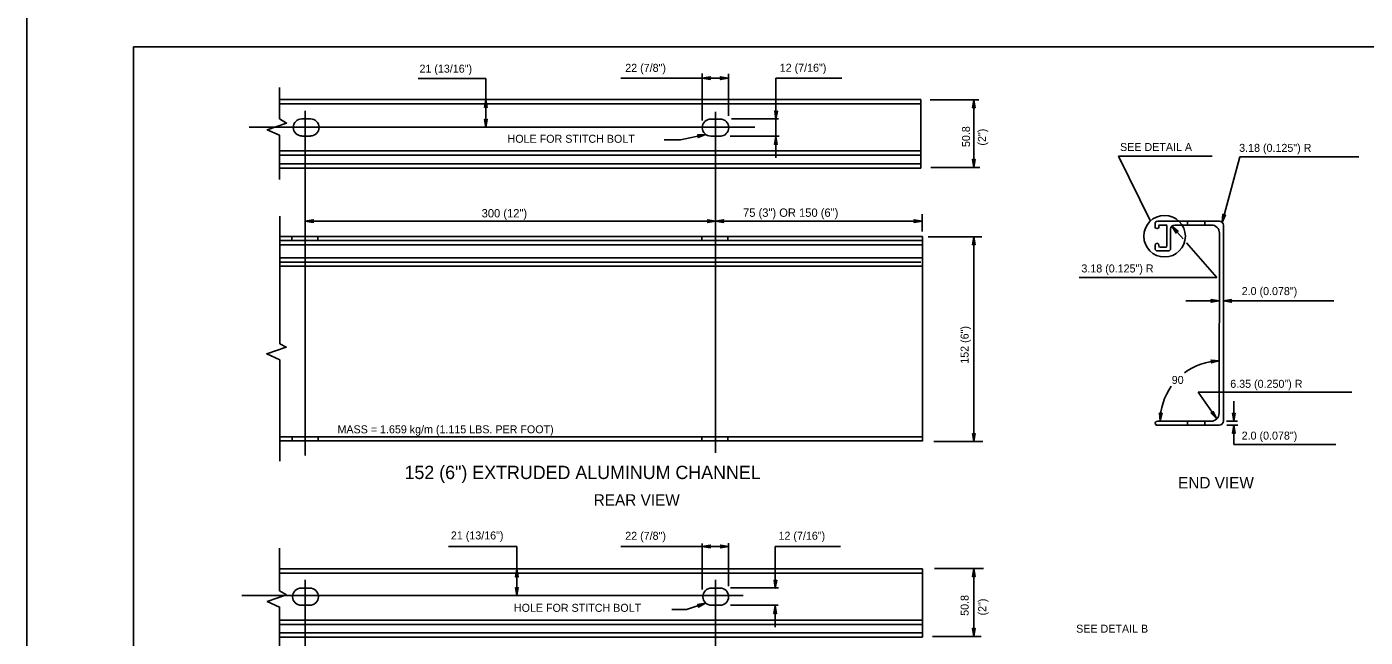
# Model space of a CAD drawing. Extents: x 647822 to 648727, y 298458 to 299646.
# Drawn here: x 647822 to 648324, y 298815 to 299044 of the extents above; entities that cross this region are included whole.
import ezdxf

# ---------------------------------------------------------------- set-up
doc = ezdxf.new("R2010")
doc.units = 0
for name, color, linetype in [('1', 7, 'Continuous'), ('2', 7, 'Continuous'), ('3', 7, 'Continuous'), ('XCS-GRID-MIN', 7, 'Continuous')]:
    doc.layers.add(name, color=color, linetype=linetype)

# ---------------------------------------------------------------- blocks, each defined once
blk = doc.blocks.new('RARROW')
at = {"layer": '3'}
blk.add_lwpolyline([(-2.2695, 0.285), (-2.184875, 0.12075), (0, 0), (-2.2695, 0.285), (-2.38575, 0.384625), (0, 0), (-2.183125, -0.108), (-2.262875, -0.2705), (0, 0), (-2.38575, -0.379125), (-2.262875, -0.2705)], dxfattribs=at)

msp = doc.modelspace()

# ---------------------------------------------------------------- linework, layer by layer
at = {"layer": '1'}
for q in [(648648.31, 299036.63), (647862.31, 298472.63)]:
    msp.add_line((647862.31, 299036.63), q, dxfattribs=at)
at = {"layer": '2'}
for p, q in [((648075.56, 299008.97), (648075.56, 299026.6)), ((648085.44, 299010.72), (648085.44, 299026.48)), ((647917.06, 299021.35), (647917.06, 299009.6)), ((647994.44, 299024.72), (647969.05, 299024.72)), ((647994.44, 299016.47), (647994.44, 299024.72)), ((648075.44, 299024.85), (648045.05, 299024.85)), ((648075.69, 299024.85), (648066.06, 299024.85)), ((648085.31, 299024.85), (648075.56, 299024.85)), ((648085.44, 299024.85), (648085.06, 299024.85)), ((648085.44, 299024.85), (648085.31, 299024.85)), ((648103.19, 299009.47), (648103.19, 299024.85)), ((648127.83, 299024.85), (648103.19, 299024.85)), ((648157.44, 299016.85), (647917.06, 299016.85)), ((648157.44, 299015.22), (647917.06, 299015.22)), ((647994.44, 299006.35), (647994.44, 299016.85)), ((647994.44, 299015.22), (647994.44, 299016.6)), ((648157.44, 299016.85), (648157.44, 298991.1)), ((648179.19, 299016.72), (648160.94, 299016.72)), ((648177.31, 298991.35), (648177.31, 299016.72)), ((647926.69, 298883.22), (647926.69, 299012.6)), ((648080.56, 299012.22), (648080.56, 298884.22)), ((647905.69, 299006.47), (648095.31, 299006.47)), ((647922.19, 299006.35), (647922.19, 299006.35)), ((647922.19, 299006.35), (647922.19, 299006.35)), ((647928.69, 299009.6), (647925.44, 299009.6)), ((647928.69, 299009.6), (647925.44, 299009.6)), ((647927.06, 299006.35), (647927.06, 299006.35)), ((647927.06, 299006.35), (647927.06, 299006.35)), ((647931.94, 299006.35), (647931.94, 299006.35)), ((647931.94, 299006.35), (647931.94, 299006.35)), ((648075.81, 299006.35), (648075.81, 299006.35)), ((648075.81, 299006.35), (648075.81, 299006.35)), ((648076.19, 299006.35), (648076.19, 299006.35)), ((648076.19, 299006.35), (648076.19, 299006.35)), ((648082.31, 299009.47), (648078.69, 299009.47)), ((648080.69, 299006.35), (648080.69, 299006.35)), ((648080.69, 299006.35), (648080.69, 299006.35)), ((648081.06, 299006.35), (648081.06, 299006.35)), ((648081.06, 299006.35), (648081.06, 299006.35)), ((648085.44, 299006.35), (648085.44, 299006.35)), ((648085.44, 299006.35), (648085.44, 299006.35)), ((648085.94, 299006.35), (648085.94, 299006.35)), ((648085.94, 299006.35), (648085.94, 299006.35)), ((648104.19, 299009.6), (648086.56, 299009.6)), ((648103.19, 299002.97), (648103.19, 299009.47)), ((647917.06, 299003.47), (647917.06, 298986.85)), ((647925.44, 299003.1), (647928.69, 299003.1)), ((647925.44, 299003.1), (647928.69, 299003.1)), ((648061.31, 299001.72), (648067.44, 299001.72)), ((648076.81, 299003.72), (648067.44, 299001.72)), ((648078.81, 299003.1), (648082.69, 299003.1)), ((648104.44, 299003.1), (648086.06, 299003.1)), ((648103.19, 298994.97), (648103.19, 299002.97)), ((648157.44, 298997.6), (647917.06, 298997.6)), ((648157.44, 298995.97), (647917.06, 298995.97)), ((648243.55, 298971.13), (648231.58, 298995.54)), ((648266.76, 298995.54), (648231.58, 298995.54)), ((648270.43, 298970.75), (648277.13, 298995.32)), ((648321.74, 298995.32), (648277.13, 298995.32)), ((648157.44, 298992.72), (647917.06, 298992.72)), ((648157.44, 298991.1), (647917.06, 298991.1)), ((648179.56, 298991.35), (648161.19, 298991.35)), ((647917.19, 298973.1), (647917.19, 298925.22)), ((648080.56, 298971.22), (647926.69, 298971.22)), ((648157.94, 298971.22), (648080.56, 298971.22)), ((648157.94, 298967.35), (648157.94, 298973.85)), ((648245.3, 298970.38), (648245.3, 298969)), ((648269.43, 298971.13), (648246.18, 298971.13)), ((648249.3, 298969.75), (648247.18, 298969.75)), ((648266.43, 298969.75), (648252.68, 298969.75)), ((648257.43, 298971.13), (648257.43, 298969.75)), ((648263.93, 298969.75), (648263.93, 298971.13)), ((648158.06, 298965.47), (647917.19, 298965.47)), ((647921.69, 298963.97), (647921.69, 298965.47)), ((647931.44, 298963.97), (647931.44, 298965.47)), ((648075.44, 298963.85), (648075.44, 298965.47)), ((648085.19, 298963.97), (648085.19, 298965.47)), ((648158.06, 298965.47), (648158.06, 298888.6)), ((648180.31, 298965.35), (648160.19, 298965.35)), ((648177.31, 298888.47), (648177.31, 298965.35)), ((648246.18, 298968.38), (648245.93, 298968.38)), ((648246.68, 298969.38), (648246.68, 298969)), ((648249.68, 298961.88), (648249.68, 298969.38)), ((648251.05, 298960.88), (648251.05, 298968.13)), ((648255.78, 298964.56), (648251.59, 298969.33)), ((648269.3, 298899.12), (648269.43, 298966.75)), ((648270.93, 298896.23), (648270.93, 298969.63)), ((648158.06, 298963.97), (647917.19, 298963.97)), ((648158.06, 298962.35), (647917.19, 298962.35)), ((648245.3, 298962.25), (648245.3, 298960.88)), ((648245.93, 298962.88), (648246.18, 298962.88)), ((648246.18, 298960), (648250.3, 298960)), ((648246.68, 298962.25), (648246.68, 298961.88)), ((648247.18, 298961.38), (648249.3, 298961.38)), ((648268.52, 298950.06), (648257.11, 298963.04)), ((648158.06, 298957.47), (647917.19, 298957.47)), ((648157.44, 298955.85), (647917.19, 298955.85)), ((648158.06, 298954.35), (647917.19, 298954.35)), ((648268.52, 298950.06), (648216.83, 298950.06)), ((648269.3, 298941.25), (648256.8, 298941.25)), ((648312.34, 298941.25), (648270.93, 298941.25)), ((647917.19, 298919.22), (647917.19, 298881.1)), ((648319.02, 298907), (648261.43, 298907)), ((648268.43, 298897), (648261.43, 298907)), ((648274.8, 298896.13), (648274.8, 298903.63)), ((648266.3, 298896.13), (648246.18, 298896.13)), ((648269.33, 298894.63), (648246.18, 298894.63)), ((648257.43, 298896.13), (648257.43, 298894.63)), ((648263.93, 298894.63), (648263.93, 298896.13)), ((648276.18, 298896.13), (648272.05, 298896.13)), ((648276.3, 298894.63), (648272.18, 298894.63)), ((648274.8, 298887.38), (648274.8, 298894.63)), ((648158.06, 298890.22), (647917.19, 298890.22)), ((647921.81, 298888.72), (647921.81, 298890.22)), ((647931.56, 298888.72), (647931.56, 298890.22)), ((648075.44, 298888.6), (648075.44, 298890.22)), ((648085.19, 298888.6), (648085.19, 298890.22)), ((648158.06, 298888.72), (647917.19, 298888.72)), ((648180.69, 298888.47), (648162.31, 298888.47)), ((648313.02, 298887.38), (648274.8, 298887.38)), ((648075.56, 298833), (648075.56, 298850.27)), ((648085.44, 298834.25), (648085.44, 298850.4)), ((647917.06, 298848.5), (647917.06, 298832.5)), ((647980.36, 298849.15), (648006.06, 298849.15)), ((648006.06, 298840.75), (648006.06, 298849.15)), ((648045.05, 298849.15), (648075.56, 298849.15)), ((648085.44, 298849.15), (648075.56, 298849.15)), ((648102.94, 298833.5), (648102.94, 298849.15)), ((648102.94, 298849.15), (648127.37, 298849.15)), ((648158.06, 298840.75), (647917.06, 298840.75)), ((648006.06, 298840.75), (648006.06, 298841)), ((648006.06, 298840.75), (648006.06, 298830.75)), ((648158.06, 298840.75), (648158.06, 298815.13)), ((648180.94, 298840.88), (648162.56, 298840.88)), ((648177.31, 298815.38), (648177.31, 298840.88)), ((648158.06, 298839.13), (647917.06, 298839.13)), ((647926.69, 298625.88), (647926.69, 298836.63)), ((648080.56, 298836.63), (648080.56, 298658.79)), ((647902.94, 298830.75), (648090.94, 298830.75)), ((647921.94, 298830.38), (647921.94, 298830.38)), ((647921.94, 298830.38), (647921.94, 298830.38)), ((647928.44, 298833.5), (647925.19, 298833.5)), ((647928.44, 298833.5), (647925.19, 298833.5)), ((647926.81, 298830.38), (647926.81, 298830.38)), ((647926.81, 298830.38), (647926.81, 298830.38)), ((647931.56, 298830.38), (647931.56, 298830.38)), ((647931.56, 298830.38), (647931.56, 298830.38)), ((648075.81, 298830.38), (648075.81, 298830.38)), ((648075.81, 298830.38), (648075.81, 298830.38)), ((648082.19, 298833.5), (648078.94, 298833.5)), ((648082.19, 298833.5), (648078.94, 298833.5)), ((648080.56, 298830.38), (648080.56, 298830.38)), ((648080.56, 298830.38), (648080.56, 298830.38)), ((648085.44, 298830.38), (648085.44, 298830.38)), ((648085.44, 298830.38), (648085.44, 298830.38)), ((648104.19, 298833.63), (648086.19, 298833.63)), ((647917.06, 298826.5), (647917.06, 298808.25)), ((647925.19, 298827.13), (647928.44, 298827.13)), ((647925.19, 298827.13), (647928.44, 298827.13)), ((648064.19, 298825.5), (648069.69, 298825.5)), ((648076.81, 298827.88), (648069.69, 298825.5)), ((648078.94, 298827.13), (648082.19, 298827.13)), ((648078.94, 298827.13), (648082.19, 298827.13)), ((648104.06, 298827.13), (648086.19, 298827.13)), ((648102.94, 298818.88), (648102.94, 298827)), ((648158.06, 298821.5), (647917.06, 298821.5)), ((648158.06, 298819.88), (647917.06, 298819.88)), ((648158.06, 298816.75), (647917.06, 298816.75)), ((648158.06, 298815.13), (647917.06, 298815.13)), ((648180.06, 298815.38), (648161.81, 298815.38))]:
    msp.add_line(p, q, dxfattribs=at)
for points in [[(647917.06, 299003.47), (647912.44, 299005.47), (647919.69, 299007.97), (647917.06, 299009.6)], [(647917.19, 298919.22), (647912.31, 298921.47), (647919.56, 298923.97), (647917.19, 298925.22)], [(647917.06, 298826.38), (647912.44, 298828.5), (647919.69, 298831), (647917.06, 298832.5)]]:
    msp.add_lwpolyline(points, dxfattribs=at)
msp.add_circle((648248.88, 298965.55), 7.8, dxfattribs=at)
for centre, radius, start, end in [((647925.43, 299006.37), 3.2, 90, 180), ((647925.43, 299006.37), 3.2, 90, 180), ((647925.43, 299006.36), 3.2, 180, 270), ((647925.43, 299006.36), 3.2, 180, 270), ((647928.68, 299006.37), 3.2, 0, 90), ((647928.68, 299006.37), 3.2, 0, 90), ((647928.68, 299006.36), 3.2, 270, 0), ((647928.68, 299006.36), 3.2, 270, 0), ((648078.77, 299006.29), 3.2, 90, 180), ((648078.77, 299006.28), 3.2, 180, 270), ((648082.29, 299006.29), 3.2, 0, 90), ((648082.29, 299006.29), 3.2, 0, 90), ((648082.29, 299006.28), 3.2, 270, 0), ((648082.29, 299006.28), 3.2, 270, 0), ((648246.11, 298970.38), 0.795, 90, 180), ((648247.12, 298969.39), 0.398, 90, 180), ((648249.31, 298969.39), 0.398, 0, 90), ((648252.68, 298968.13), 1.62, 90, 180), ((648266.43, 298966.75), 3, 359.8939, 90), ((648269.43, 298969.63), 1.5, 0, 90), ((648245.92, 298969), 0.612, 180, 270), ((648246.11, 298969), 0.612, 270, 0), ((648245.92, 298962.21), 0.612, 90, 180), ((648246.11, 298960.82), 0.795, 180, 270), ((648246.11, 298962.21), 0.612, 0, 90), ((648247.12, 298961.82), 0.398, 180, 270), ((648249.31, 298961.82), 0.398, 270, 0), ((648250.3, 298960.82), 0.795, 270, 0), ((648269.79, 298896.24), 22.55, 91.156, 126.6633), ((648269.79, 298896.24), 22.55, 144.8324, 180.2847), ((648246.07, 298895.38), 0.758, 81.3591, 278.1482), ((648266.3, 298899.13), 3, 270, 359.8939), ((648269.33, 298896.23), 1.6, 270, 0), ((647925.18, 298830.32), 3.2, 90, 180), ((647925.18, 298830.32), 3.2, 90, 180), ((647925.18, 298830.31), 3.2, 180, 270), ((647925.18, 298830.31), 3.2, 180, 270), ((647928.42, 298830.32), 3.2, 0, 90), ((647928.42, 298830.32), 3.2, 0, 90), ((647928.42, 298830.31), 3.2, 270, 0), ((647928.42, 298830.31), 3.2, 270, 0), ((648078.98, 298830.32), 3.2, 90, 180), ((648078.98, 298830.32), 3.2, 90, 180), ((648078.98, 298830.31), 3.2, 180, 270), ((648078.98, 298830.31), 3.2, 180, 270), ((648082.22, 298830.32), 3.2, 0, 90), ((648082.22, 298830.32), 3.2, 0, 90), ((648082.22, 298830.31), 3.2, 270, 0), ((648082.22, 298830.31), 3.2, 270, 0)]:
    msp.add_arc(centre, radius, start, end, dxfattribs=at)
at = {"layer": 'XCS-GRID-MIN'}
msp.add_lwpolyline([(647822.31, 299051.63), (648663.31, 299051.63), (648663.31, 298457.63), (647822.31, 298457.63)], close=True, dxfattribs=at)

# ---------------------------------------------------------------- block references
at = {"layer": '2', "xscale": 1.2574347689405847}
for p, yscale, rotation in [((648075.56, 299024.85), 1.3092961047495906, 180), ((647994.44, 299016.85), 1.3092961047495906, 89.99999999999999), ((648177.31, 299016.72), 1.3092961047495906, 89.99999999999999), ((648103.19, 299009.47), 1.3092961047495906, -90.00000000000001), ((647994.44, 299006.35), 1.3092961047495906, -90.00000000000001), ((648076.81, 299003.72), 1.3092961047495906, 12.912406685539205), ((648103.19, 299002.97), 1.3092961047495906, 89.99999999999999), ((648177.31, 298991.35), 1.3092961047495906, -90.00000000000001), ((647926.69, 298971.22), 1.3092961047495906, 180), ((648080.56, 298971.22), 1.3092961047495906, 180), ((648270.43, 298970.75), 1.3092961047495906, -104.793858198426), ((648177.31, 298965.35), 1.3092961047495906, 89.99999999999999), ((648251.59, 298969.33), 1.3092961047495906, 131.44756539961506), ((648270.93, 298941.25), 1.3092961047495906, 180), ((648269.34, 298918.78), 1.3092961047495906, 4.548170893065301), ((648268.43, 298897), 1.3092961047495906, -55.09389984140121), ((648247.25, 298896.16), 1.3092961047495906, -92.99557749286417), ((648274.8, 298894.63), 1.3092961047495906, 89.99999999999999), ((648274.8, 298896.13), 1.3092961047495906, -90.00000000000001), ((648177.31, 298888.47), 1.3092961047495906, -90.00000000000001), ((648075.56, 298849.15), 1.3092961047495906, 180), ((648006.06, 298840.75), 1.3092961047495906, 89.99999999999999), ((648177.31, 298840.88), 1.3092961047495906, 89.99999999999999), ((648102.94, 298833.5), 1.3092961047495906, -90.00000000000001), ((648006.06, 298830.75), 1.3092961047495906, -90.00000000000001), ((648076.81, 298827.88), 1.3092961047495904, 19.076864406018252), ((648102.94, 298827), 1.3092961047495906, 89.99999999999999), ((648177.31, 298815.38), 1.3092961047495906, -90.00000000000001)]:
    msp.add_blockref('RARROW', p, dxfattribs=dict(at, yscale=yscale, rotation=rotation))
at = {"layer": '2', "xscale": 1.2574347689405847, "yscale": 1.3092961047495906}
for p in [(648085.31, 299024.85), (648080.56, 298971.22), (648157.94, 298971.22), (648269.3, 298941.25), (648085.44, 298849.15)]:
    msp.add_blockref('RARROW', p, dxfattribs=at)

# ---------------------------------------------------------------- texts
at = {"layer": '2'}
for s, height, p in [('21 (13/16") ', 3, (647969.54, 299026.9)), ('22 (7/8")', 3, (648046.68, 299027.21)), ('12 (7/16") ', 3, (648104.59, 299027.25)), ('HOLE FOR STITCH BOLT', 3, (648002.56, 299000.6)), ('SEE DETAIL A', 3, (648232.18, 298997.52)), ('3.18 (0.125") R', 3, (648276.84, 298997.19)), ('300 (12")', 3.125, (647992.84, 298972.6)), ('75 (3") OR 150 (6")', 3.1252, (648090.84, 298972.82)), ('3.18 (0.125") R', 3, (648217.68, 298951.95)), ('2.0 (0.078") ', 3, (648277.77, 298943.45)), ('90', 3, (648251.55, 298910.13)), ('6.35 (0.250") R', 3, (648273.49, 298908.67)), ('MASS = 1.659 kg/m (1.115 LBS. PER FOOT)', 3, (647938.8, 298891.6)), ('2.0 (0.078") ', 3, (648277.77, 298889.24)), ('152 (6") EXTRUDED ALUMINUM CHANNEL', 5, (647963.92, 298874.44)), ('END VIEW', 4.3, (648253.93, 298870.92)), ('REAR VIEW', 4.3, (648034.85, 298864.44)), ('21 (13/16") ', 3, (647981.31, 298851.78)), ('22 (7/8")', 3, (648046.68, 298851.64)), ('12 (7/16") ', 3, (648104.14, 298851.67)), ('HOLE FOR STITCH BOLT', 3, (648004.94, 298824.63)), ('SEE DETAIL B', 3, (648215.73, 298816.8))]:
    msp.add_text(s, height=height, dxfattribs=at).set_placement(p)
for s, p in [('50.8', (648175.91, 298999)), ('(2")', (648181.89, 298999.54)), ('152 (6")', (648175.4, 298917.71)), ('50.8', (648175.41, 298823.13)), ('(2")', (648181.99, 298823.27))]:
    msp.add_text(s, height=3, rotation=90, dxfattribs=at).set_placement(p)

doc.saveas('drawing.dxf')
